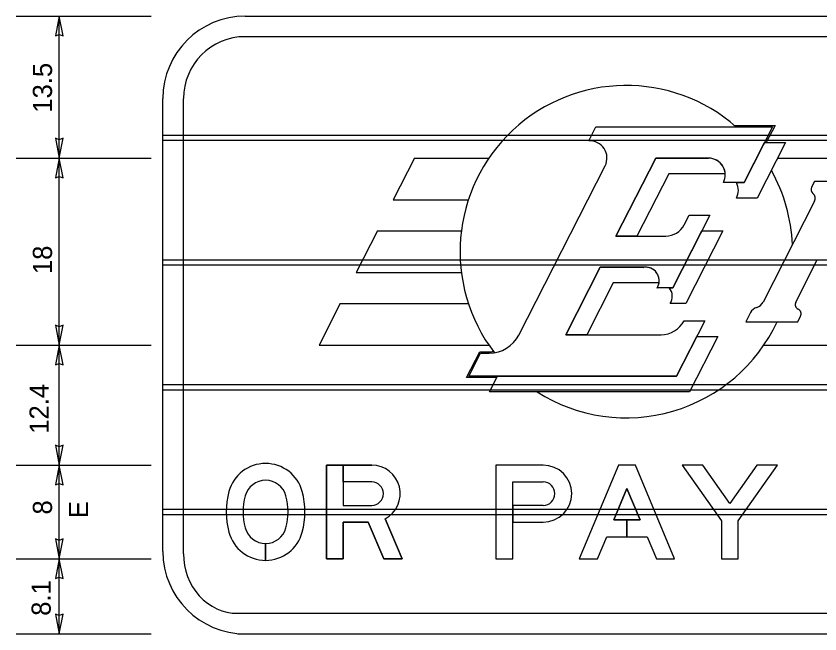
# Model space of a CAD drawing. Extents: x 319706 to 320449, y 1621775 to 1622117.
# Drawn here: x 319820.5 to 319879.3, y 1621943.1 to 1621988.3 of the extents above; entities that cross this region are included whole.
import ezdxf

# ---------------------------------------------------------------- set-up
doc = ezdxf.new("R2010")
doc.units = 0
for name, color, linetype in [('1', 7, 'Continuous'), ('52', 7, 'Continuous'), ('GSBWFill', 7, 'Continuous'), ('GSColorFill', 7, 'Continuous'), ('GSOutline', 7, 'Continuous'), ('SignPanel', 7, 'Continuous')]:
    doc.layers.add(name, color=color, linetype=linetype)

msp = doc.modelspace()

# ---------------------------------------------------------------- linework, layer by layer
at = {"layer": '1'}
for p, q in [((319820.542, 1621988.266), (319830.406, 1621988.266)), ((319823.703, 1621977.877), (319823.703, 1621988.266)), ((319820.542, 1621977.877), (319830.406, 1621977.877)), ((319823.703, 1621964.207), (319823.703, 1621977.877)), ((319820.542, 1621964.207), (319830.406, 1621964.207)), ((319823.703, 1621955.434), (319823.703, 1621964.207)), ((319820.542, 1621955.434), (319830.406, 1621955.434)), ((319823.703, 1621948.592), (319823.703, 1621955.434)), ((319820.542, 1621948.592), (319830.406, 1621948.592)), ((319823.703, 1621943.091), (319823.703, 1621948.592)), ((319820.542, 1621943.091), (319830.406, 1621943.091))]:
    msp.add_line(p, q, dxfattribs=at)
at = {"layer": '52'}
for p, q in [((319823.703, 1621988.266), (319823.423, 1621986.816)), ((319823.973, 1621986.816), (319823.703, 1621988.266)), ((319823.423, 1621986.816), (319823.703, 1621986.926)), ((319823.703, 1621986.926), (319823.973, 1621986.816)), ((319823.703, 1621979.217), (319823.433, 1621979.327)), ((319823.433, 1621979.327), (319823.703, 1621977.877)), ((319823.703, 1621977.877), (319823.983, 1621979.327)), ((319823.983, 1621979.327), (319823.703, 1621979.217)), ((319823.703, 1621977.877), (319823.423, 1621976.427)), ((319823.973, 1621976.427), (319823.703, 1621977.877)), ((319823.423, 1621976.427), (319823.703, 1621976.537)), ((319823.703, 1621976.537), (319823.973, 1621976.427)), ((319823.703, 1621965.547), (319823.433, 1621965.657)), ((319823.433, 1621965.657), (319823.703, 1621964.207)), ((319823.703, 1621964.207), (319823.983, 1621965.657)), ((319823.983, 1621965.657), (319823.703, 1621965.547)), ((319823.703, 1621964.207), (319823.423, 1621962.757)), ((319823.973, 1621962.757), (319823.703, 1621964.207)), ((319823.423, 1621962.757), (319823.703, 1621962.867)), ((319823.703, 1621962.867), (319823.973, 1621962.757)), ((319823.703, 1621956.774), (319823.433, 1621956.884)), ((319823.433, 1621956.884), (319823.703, 1621955.434)), ((319823.703, 1621955.434), (319823.983, 1621956.884)), ((319823.983, 1621956.884), (319823.703, 1621956.774)), ((319823.703, 1621955.434), (319823.423, 1621953.984)), ((319823.973, 1621953.984), (319823.703, 1621955.434)), ((319823.423, 1621953.984), (319823.703, 1621954.094)), ((319823.703, 1621954.094), (319823.973, 1621953.984)), ((319823.703, 1621949.932), (319823.433, 1621950.042)), ((319823.433, 1621950.042), (319823.703, 1621948.592)), ((319823.703, 1621948.592), (319823.983, 1621950.042)), ((319823.983, 1621950.042), (319823.703, 1621949.932)), ((319823.703, 1621948.592), (319823.423, 1621947.142)), ((319823.973, 1621947.142), (319823.703, 1621948.592)), ((319823.423, 1621947.142), (319823.703, 1621947.252)), ((319823.703, 1621947.252), (319823.973, 1621947.142)), ((319823.703, 1621944.431), (319823.433, 1621944.541)), ((319823.433, 1621944.541), (319823.703, 1621943.091)), ((319823.703, 1621943.091), (319823.983, 1621944.541)), ((319823.983, 1621944.541), (319823.703, 1621944.431))]:
    msp.add_line(p, q, dxfattribs=at)
at = {"layer": 'GSBWFill'}
for p, q in [((319856.84, 1621954.202), (319859.064, 1621954.202)), ((319838.779, 1621948.473), (319838.779, 1621949.704)), ((319838.779, 1621949.704), (319838.779, 1621948.473))]:
    msp.add_line(p, q, dxfattribs=at)
for points in [[(319847.507, 1621951.502), (319848.767, 1621948.592), (319847.425, 1621948.592), (319846.27, 1621951.261), (319844.457, 1621951.261), (319844.457, 1621948.592), (319843.226, 1621948.592), (319843.226, 1621955.434), (319844.457, 1621955.434), (319844.457, 1621952.492), (319846.533, 1621952.492)], [(319844.457, 1621954.202), (319844.457, 1621955.434), (319846.533, 1621955.434)], [(319859.064, 1621955.434), (319855.609, 1621955.434), (319855.609, 1621948.592), (319856.84, 1621948.592), (319856.84, 1621954.202)], [(319846.533, 1621954.202), (319844.457, 1621954.202)], [(319859.064, 1621952.492), (319856.841, 1621952.492), (319856.841, 1621951.261), (319859.064, 1621951.261)]]:
    msp.add_lwpolyline(points, dxfattribs=at)
for points in [[(319866.148, 1621951.432), (319865.187, 1621951.432), (319865.187, 1621950.2), (319866.665, 1621950.2), (319867.34, 1621948.592), (319868.676, 1621948.592), (319865.803, 1621955.434), (319864.571, 1621955.434), (319861.698, 1621948.592), (319863.033, 1621948.592), (319863.709, 1621950.2), (319865.187, 1621950.2), (319865.187, 1621951.432), (319864.226, 1621951.432), (319865.187, 1621953.72)], [(319873.328, 1621951.363), (319876.202, 1621955.434), (319874.694, 1621955.434), (319872.713, 1621952.626), (319870.731, 1621955.434), (319869.223, 1621955.434), (319872.097, 1621951.363), (319872.097, 1621948.592), (319873.328, 1621948.592)]]:
    msp.add_lwpolyline(points, close=True, dxfattribs=at)
for centre, radius, start, end in [((319838.779, 1621952.781), 2.773, 14.96177, 165.03823), ((319846.533, 1621953.347), 2.087, 297.837, 90), ((319838.779, 1621952.781), 1.541, 14.96177, 165.03823), ((319846.533, 1621953.347), 0.855, 270, 90), ((319841.652, 1621952.013), 5.747, 165.03823, 194.96177), ((319835.905, 1621952.013), 5.747, 345.03823, 14.96177), ((319841.652, 1621952.013), 4.515, 165.03823, 194.96177), ((319835.905, 1621952.013), 4.515, 345.03823, 14.96177), ((319838.779, 1621951.245), 2.773, 194.96177, 270), ((319838.779, 1621951.245), 1.541, 194.96177, 270), ((319838.779, 1621951.245), 1.541, 270.01272, 345.03823), ((319838.779, 1621951.245), 2.773, 270.00707, 345.03823)]:
    msp.add_arc(centre, radius, start, end, dxfattribs=at)
for major_axis in [(0, 2.087), (0, 0.855)]:
    msp.add_ellipse((319859.064, 1621953.347), major_axis=major_axis, ratio=0.999994, start_param=3.141593, end_param=6.283185, dxfattribs=at)
at = {"layer": 'GSColorFill'}
for p, q in [((319856.84, 1621954.202), (319859.064, 1621954.202)), ((319838.779, 1621948.473), (319838.779, 1621949.704)), ((319838.779, 1621949.704), (319838.779, 1621948.473))]:
    msp.add_line(p, q, dxfattribs=at)
for points in [[(319847.507, 1621951.502), (319848.767, 1621948.592), (319847.425, 1621948.592), (319846.27, 1621951.261), (319844.457, 1621951.261), (319844.457, 1621948.592), (319843.226, 1621948.592), (319843.226, 1621955.434), (319844.457, 1621955.434), (319844.457, 1621952.492), (319846.533, 1621952.492)], [(319844.457, 1621954.202), (319844.457, 1621955.434), (319846.533, 1621955.434)], [(319859.064, 1621955.434), (319855.609, 1621955.434), (319855.609, 1621948.592), (319856.84, 1621948.592), (319856.84, 1621954.202)], [(319846.533, 1621954.202), (319844.457, 1621954.202)], [(319859.064, 1621952.492), (319856.841, 1621952.492), (319856.841, 1621951.261), (319859.064, 1621951.261)]]:
    msp.add_lwpolyline(points, dxfattribs=at)
for points in [[(319866.148, 1621951.432), (319865.187, 1621951.432), (319865.187, 1621950.2), (319866.665, 1621950.2), (319867.34, 1621948.592), (319868.676, 1621948.592), (319865.803, 1621955.434), (319864.571, 1621955.434), (319861.698, 1621948.592), (319863.033, 1621948.592), (319863.709, 1621950.2), (319865.187, 1621950.2), (319865.187, 1621951.432), (319864.226, 1621951.432), (319865.187, 1621953.72)], [(319873.328, 1621951.363), (319876.202, 1621955.434), (319874.694, 1621955.434), (319872.713, 1621952.626), (319870.731, 1621955.434), (319869.223, 1621955.434), (319872.097, 1621951.363), (319872.097, 1621948.592), (319873.328, 1621948.592)]]:
    msp.add_lwpolyline(points, close=True, dxfattribs=at)
for centre, radius, start, end in [((319838.779, 1621952.781), 2.773, 14.96177, 165.03823), ((319846.533, 1621953.347), 2.087, 297.837, 90), ((319838.779, 1621952.781), 1.541, 14.96177, 165.03823), ((319846.533, 1621953.347), 0.855, 270, 90), ((319841.652, 1621952.013), 5.747, 165.03823, 194.96177), ((319835.905, 1621952.013), 5.747, 345.03823, 14.96177), ((319841.652, 1621952.013), 4.515, 165.03823, 194.96177), ((319835.905, 1621952.013), 4.515, 345.03823, 14.96177), ((319838.779, 1621951.245), 2.773, 194.96177, 270), ((319838.779, 1621951.245), 1.541, 194.96177, 270), ((319838.779, 1621951.245), 1.541, 270.01272, 345.03823), ((319838.779, 1621951.245), 2.773, 270.00707, 345.03823)]:
    msp.add_arc(centre, radius, start, end, dxfattribs=at)
for major_axis in [(0, 2.087), (0, 0.855)]:
    msp.add_ellipse((319859.064, 1621953.347), major_axis=major_axis, ratio=0.999994, start_param=3.141593, end_param=6.283185, dxfattribs=at)
at = {"layer": 'GSOutline'}
for p, q in [((319856.84, 1621954.202), (319859.064, 1621954.202)), ((319856.84, 1621951.261), (319859.064, 1621951.261))]:
    msp.add_line(p, q, dxfattribs=at)
for points in [[(319846.533, 1621955.434), (319843.226, 1621955.434), (319843.226, 1621948.592), (319844.457, 1621948.592), (319844.457, 1621951.261), (319846.27, 1621951.261), (319847.425, 1621948.592), (319848.767, 1621948.592), (319847.507, 1621951.502)], [(319859.064, 1621955.434), (319855.609, 1621955.434), (319855.609, 1621948.592), (319856.84, 1621948.592), (319856.84, 1621951.261)], [(319846.533, 1621954.202), (319844.457, 1621954.202), (319844.457, 1621952.492), (319846.533, 1621952.492)], [(319859.064, 1621952.492), (319856.84, 1621952.492), (319856.84, 1621954.202)]]:
    msp.add_lwpolyline(points, dxfattribs=at)
for points in [[(319863.709, 1621950.2), (319866.665, 1621950.2), (319867.34, 1621948.592), (319868.676, 1621948.592), (319865.803, 1621955.434), (319864.571, 1621955.434), (319861.698, 1621948.592), (319863.033, 1621948.592)], [(319873.328, 1621951.363), (319876.202, 1621955.434), (319874.694, 1621955.434), (319872.713, 1621952.626), (319870.731, 1621955.434), (319869.223, 1621955.434), (319872.097, 1621951.363), (319872.097, 1621948.592), (319873.328, 1621948.592)], [(319866.148, 1621951.432), (319865.187, 1621953.72), (319864.226, 1621951.432)]]:
    msp.add_lwpolyline(points, close=True, dxfattribs=at)
for centre, radius, start, end in [((319838.779, 1621952.781), 2.773, 14.96177, 165.03823), ((319846.533, 1621953.347), 2.087, 297.837, 90), ((319838.779, 1621952.781), 1.541, 14.96177, 165.03823), ((319846.533, 1621953.347), 0.855, 270, 90), ((319841.652, 1621952.013), 5.747, 165.03823, 194.96177), ((319835.905, 1621952.013), 5.747, 345.03823, 14.96177), ((319841.652, 1621952.013), 4.515, 165.03823, 194.96177), ((319835.905, 1621952.013), 4.515, 345.03823, 14.96177), ((319838.779, 1621951.245), 2.773, 194.96177, 345.03823), ((319838.779, 1621951.245), 1.541, 194.96177, 345.03823)]:
    msp.add_arc(centre, radius, start, end, dxfattribs=at)
for major_axis in [(0, 2.087), (0, 0.855)]:
    msp.add_ellipse((319859.064, 1621953.347), major_axis=major_axis, ratio=0.999994, start_param=3.141593, end_param=6.283185, dxfattribs=at)
at = {"layer": 'SignPanel'}
for p, q in [((319837.294, 1621988.266), (319933.667, 1621988.266)), ((319837.294, 1621986.761), (319933.667, 1621986.761)), ((319831.271, 1621949.115), (319831.271, 1621982.242)), ((319832.777, 1621948.956), (319832.777, 1621982.242)), ((319862.397, 1621979.136), (319862.914, 1621980.156)), ((319862.914, 1621980.156), (319875.826, 1621980.156)), ((319873.05, 1621980.269), (319876.01, 1621980.269)), ((319875.826, 1621980.156), (319873.758, 1621976.095)), ((319876.01, 1621980.269), (319875.373, 1621979.017)), ((319831.271, 1621979.56), (319939.691, 1621979.56)), ((319831.271, 1621979.183), (319939.691, 1621979.183)), ((319873.754, 1621976.091), (319875.245, 1621979.017)), ((319873.754, 1621976.091), (319875.245, 1621979.017)), ((319876.779, 1621979.017), (319874.71, 1621974.955)), ((319876.779, 1621979.017), (319874.71, 1621974.955)), ((319875.245, 1621979.017), (319876.779, 1621979.017)), ((319875.245, 1621979.017), (319876.779, 1621979.017)), ((319849.652, 1621977.877), (319848.105, 1621974.839)), ((319849.652, 1621977.877), (319855.098, 1621977.877)), ((319867.29, 1621977.877), (319864.388, 1621972.182)), ((319864.388, 1621972.182), (319867.29, 1621977.877)), ((319864.388, 1621972.182), (319867.29, 1621977.877)), ((319871.16, 1621977.877), (319867.29, 1621977.877)), ((319867.29, 1621977.877), (319871.16, 1621977.877)), ((319867.29, 1621977.877), (319871.16, 1621977.877)), ((319876.198, 1621977.877), (319919.522, 1621977.877)), ((319857.293, 1621964.947), (319863.597, 1621977.318)), ((319868.244, 1621976.739), (319865.922, 1621972.182)), ((319868.244, 1621976.739), (319865.922, 1621972.182)), ((319872.375, 1621976.739), (319868.244, 1621976.739)), ((319872.375, 1621976.739), (319868.244, 1621976.739)), ((319873.758, 1621976.095), (319872.238, 1621976.095)), ((319873.19, 1621976.091), (319873.754, 1621976.091)), ((319873.19, 1621976.091), (319873.754, 1621976.091)), ((319878.891, 1621976.168), (319878.683, 1621975.763)), ((319883.541, 1621976.168), (319878.891, 1621976.168)), ((319848.105, 1621974.839), (319853.602, 1621974.839)), ((319874.71, 1621974.955), (319873.192, 1621974.955)), ((319874.71, 1621974.955), (319873.192, 1621974.955)), ((319878.904, 1621974.733), (319875.143, 1621967.353)), ((319871.245, 1621973.701), (319868.537, 1621968.384)), ((319869.374, 1621973.011), (319869.726, 1621973.701)), ((319869.726, 1621973.701), (319871.245, 1621973.701)), ((319846.946, 1621972.561), (319845.399, 1621969.524)), ((319846.946, 1621972.561), (319853.087, 1621972.561)), ((319864.388, 1621972.182), (319868.022, 1621972.182)), ((319865.922, 1621972.182), (319864.388, 1621972.182)), ((319865.922, 1621972.182), (319864.388, 1621972.182)), ((319868.537, 1621968.384), (319870.665, 1621972.561)), ((319868.537, 1621968.384), (319870.665, 1621972.561)), ((319872.199, 1621972.561), (319869.49, 1621967.245)), ((319872.199, 1621972.561), (319869.49, 1621967.245)), ((319870.665, 1621972.561), (319872.199, 1621972.561)), ((319870.665, 1621972.561), (319872.199, 1621972.561)), ((319831.271, 1621970.45), (319939.691, 1621970.45)), ((319877.528, 1621967.353), (319879.099, 1621970.434)), ((319879.099, 1621970.434), (319880.238, 1621970.434)), ((319831.271, 1621970.075), (319939.691, 1621970.075)), ((319863.228, 1621969.903), (319860.712, 1621964.967)), ((319860.712, 1621964.967), (319863.228, 1621969.903)), ((319860.712, 1621964.967), (319863.228, 1621969.903)), ((319866.561, 1621969.903), (319863.228, 1621969.903)), ((319863.228, 1621969.903), (319866.417, 1621969.893)), ((319863.228, 1621969.903), (319866.417, 1621969.893)), ((319845.399, 1621969.524), (319853.087, 1621969.524)), ((319864.181, 1621968.761), (319862.246, 1621964.967)), ((319864.181, 1621968.761), (319862.246, 1621964.967)), ((319867.533, 1621968.75), (319864.181, 1621968.761)), ((319867.533, 1621968.75), (319864.181, 1621968.761)), ((319868.537, 1621968.384), (319867.393, 1621968.384)), ((319868.298, 1621968.384), (319868.537, 1621968.384)), ((319868.298, 1621968.384), (319868.537, 1621968.384)), ((319844.24, 1621967.245), (319842.694, 1621964.207)), ((319844.24, 1621967.245), (319853.602, 1621967.245)), ((319869.49, 1621967.245), (319868.351, 1621967.245)), ((319869.49, 1621967.245), (319868.351, 1621967.245)), ((319874.22, 1621966.585), (319873.878, 1621965.915)), ((319877.676, 1621965.915), (319877.882, 1621966.322)), ((319870.886, 1621965.989), (319868.817, 1621961.929)), ((319869.366, 1621965.989), (319870.886, 1621965.989)), ((319873.878, 1621965.915), (319877.676, 1621965.915)), ((319860.712, 1621964.967), (319867.683, 1621964.967)), ((319862.246, 1621964.967), (319860.712, 1621964.967)), ((319862.246, 1621964.967), (319860.712, 1621964.967)), ((319868.817, 1621961.929), (319870.305, 1621964.85)), ((319868.817, 1621961.929), (319870.305, 1621964.85)), ((319871.84, 1621964.85), (319869.77, 1621960.789)), ((319871.84, 1621964.85), (319869.77, 1621960.789)), ((319870.305, 1621964.85), (319871.84, 1621964.85)), ((319870.305, 1621964.85), (319871.84, 1621964.85)), ((319842.694, 1621964.207), (319855.098, 1621964.207)), ((319875.191, 1621964.207), (319912.556, 1621964.207)), ((319853.466, 1621961.829), (319854.429, 1621963.719)), ((319853.629, 1621961.929), (319854.491, 1621963.62)), ((319854.429, 1621963.719), (319855.127, 1621963.719)), ((319854.491, 1621963.62), (319855.127, 1621963.62)), ((319855.676, 1621961.829), (319853.466, 1621961.829)), ((319868.817, 1621961.929), (319853.629, 1621961.929)), ((319855.148, 1621960.789), (319855.727, 1621961.929)), ((319855.148, 1621960.789), (319855.727, 1621961.929)), ((319855.727, 1621961.929), (319868.817, 1621961.929)), ((319855.727, 1621961.929), (319868.817, 1621961.929)), ((319831.271, 1621961.34), (319939.691, 1621961.34)), ((319831.271, 1621960.935), (319939.691, 1621960.935)), ((319869.77, 1621960.789), (319855.148, 1621960.789)), ((319869.77, 1621960.789), (319855.148, 1621960.789)), ((319831.271, 1621952.201), (319939.691, 1621952.201)), ((319831.271, 1621951.825), (319939.691, 1621951.825)), ((319836.73, 1621944.597), (319933.667, 1621944.597)), ((319836.761, 1621943.091), (319933.667, 1621943.091))]:
    msp.add_line(p, q, dxfattribs=at)
for centre, radius, start, end in [((319837.294, 1621982.243), 6.023, 90, 180), ((319837.294, 1621982.243), 4.517, 90, 180), ((319865.144, 1621971.041), 12.151, 48.59038, 217.4727), ((319862.479, 1621977.886), 1.253, 332.99985, 93.80449), ((319871.161, 1621976.661), 1.215, 332.20885, 90), ((319871.161, 1621976.661), 1.215, 3.58332, 90), ((319871.161, 1621976.661), 1.215, 3.58332, 90), ((319865.144, 1621971.041), 12.151, 2.42356, 29.27706), ((319872.115, 1621975.522), 1.215, 332.20885, 27.91266), ((319872.115, 1621975.522), 1.215, 332.20885, 27.91266), ((319879.021, 1621975.59), 0.38, 152.97842, 231.16017), ((319878.497, 1621974.939), 0.456, 333.00266, 51.16017), ((319868.021, 1621973.7), 1.519, 270, 332.98829), ((319866.56, 1621968.915), 0.987, 350.35016, 98.33436), ((319866.56, 1621968.915), 0.987, 350.35016, 98.33436), ((319866.56, 1621968.915), 0.987, 327.42103, 90), ((319867.519, 1621967.776), 0.987, 327.42103, 37.97987), ((319867.519, 1621967.776), 0.987, 327.42103, 37.97987), ((319874.896, 1621966.24), 0.759, 106.43168, 152.97425), ((319874.466, 1621967.697), 0.759, 286.43167, 332.99588), ((319877.867, 1621967.18), 0.38, 152.98839, 244.78323), ((319877.543, 1621966.493), 0.38, 333.02391, 64.78322), ((319865.144, 1621971.041), 12.151, 237.53826, 335.04698), ((319867.681, 1621966.864), 1.899, 270, 332.5096), ((319855.127, 1621966.05), 2.43, 270, 332.99913), ((319855.127, 1621966.05), 2.332, 270, 277.50379), ((319837.294, 1621949.115), 6.023, 180, 270)]:
    msp.add_arc(centre, radius, start, end, dxfattribs=at)
msp.add_ellipse((319836.729, 1621948.957), major_axis=(0, 4.36), ratio=0.906668, start_param=1.570796, end_param=3.141593, dxfattribs=at)

# ---------------------------------------------------------------- texts
at = {"layer": '1'}
for s, p in [('13.5', (319823.169, 1621981.202)), ('18', (319823.169, 1621969.4)), ('12.4', (319822.925, 1621957.728)), ('8', (319823.169, 1621951.822)), ('E', (319825.802, 1621951.554)), ('8.1', (319823.073, 1621944.415))]:
    msp.add_text(s, height=1.4, rotation=90, dxfattribs=at).set_placement(p)

doc.saveas('drawing.dxf')
